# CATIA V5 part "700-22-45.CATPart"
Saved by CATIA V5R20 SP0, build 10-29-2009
Part number: 700-22-45
Revision: ANY
Definition: UNKNOWN
Nomenclature: 700-22-45
Source: Unknown
Bounding box of the stored display mesh (mm): x -11 to 11, y 0 to 45, z -11 to 11
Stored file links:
  C:\Users\Utente\Desktop\IO LAVORO\3D X SITO CF\X SITO\700\700-22-45.CATPart
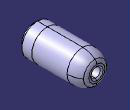
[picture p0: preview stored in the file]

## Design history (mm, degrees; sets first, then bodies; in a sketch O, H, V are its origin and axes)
Body1 "Rivoluzione1" (main body)
  Solid1: solid without history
